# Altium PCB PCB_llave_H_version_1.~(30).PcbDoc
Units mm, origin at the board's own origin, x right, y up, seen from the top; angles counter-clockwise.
Board outline 232.16 x 155.45 mm, 2 copper layers (Top Layer, Bottom Layer); 51 components, 32 nets, 157 pads, 0 vias.
Unrouted connection lines stored in the file: 59.
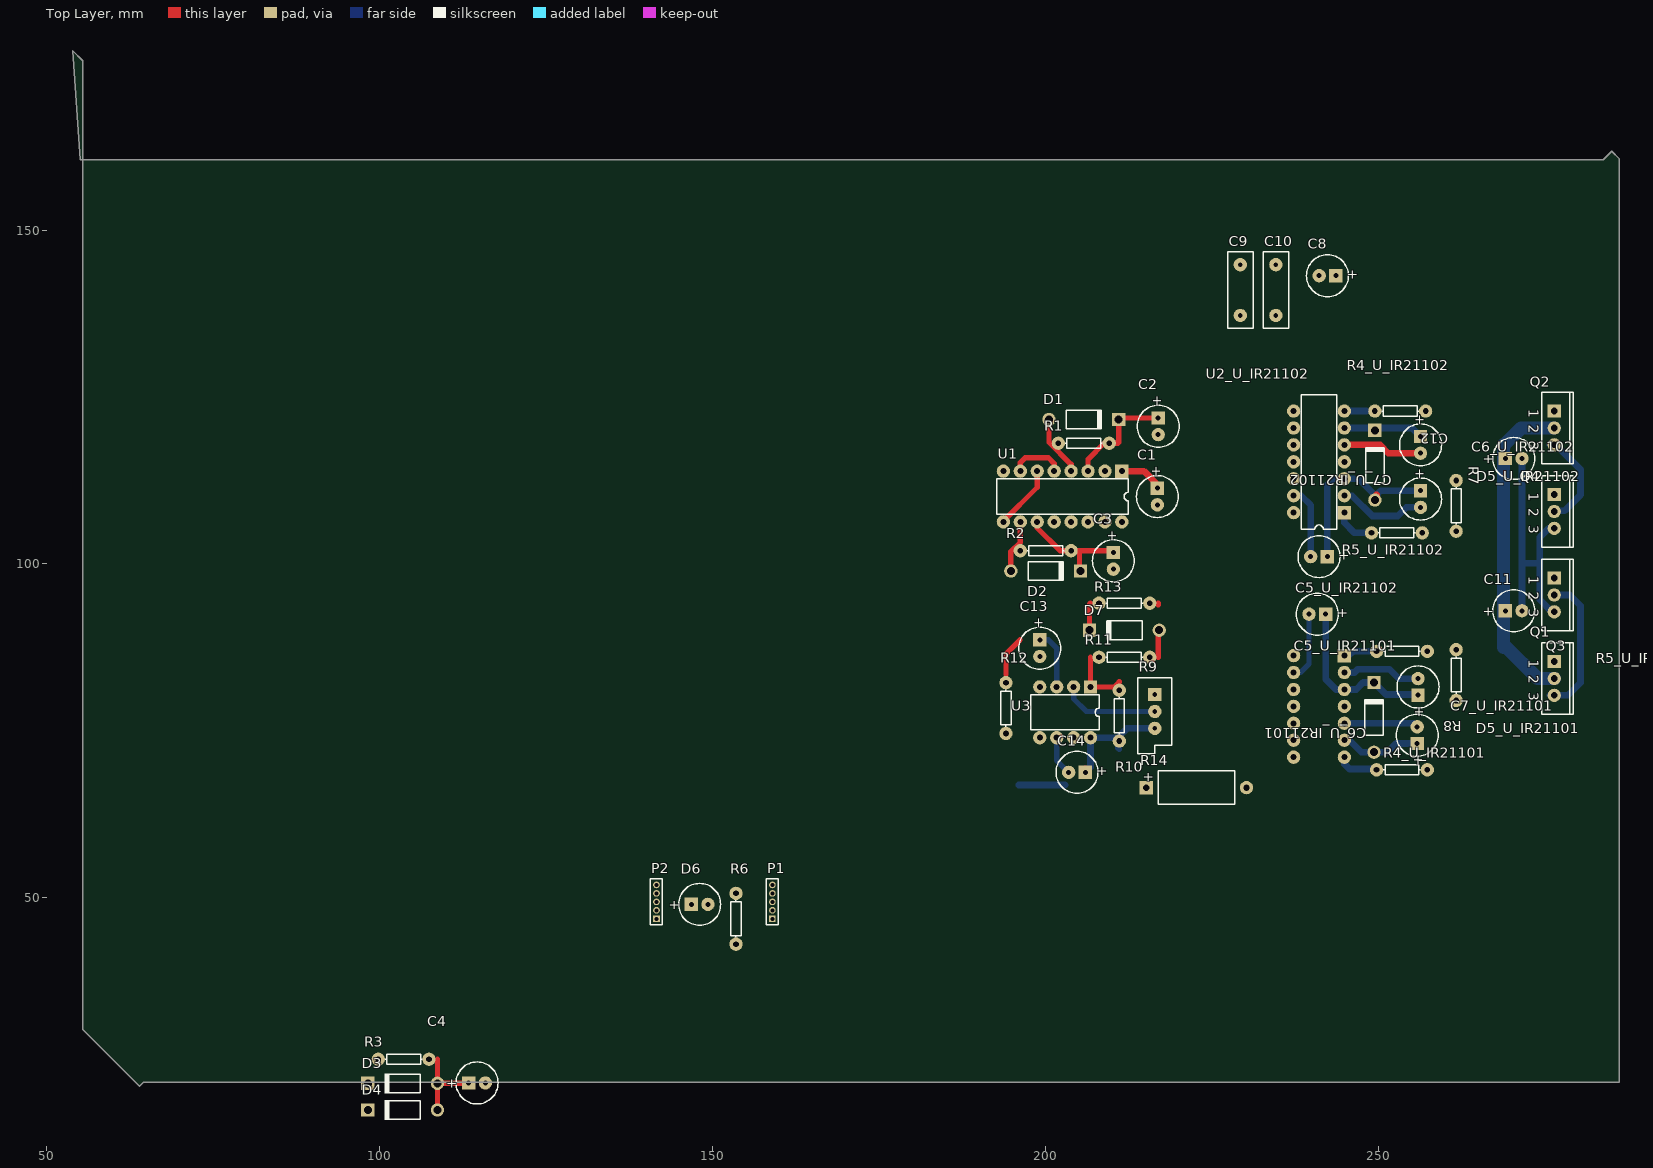
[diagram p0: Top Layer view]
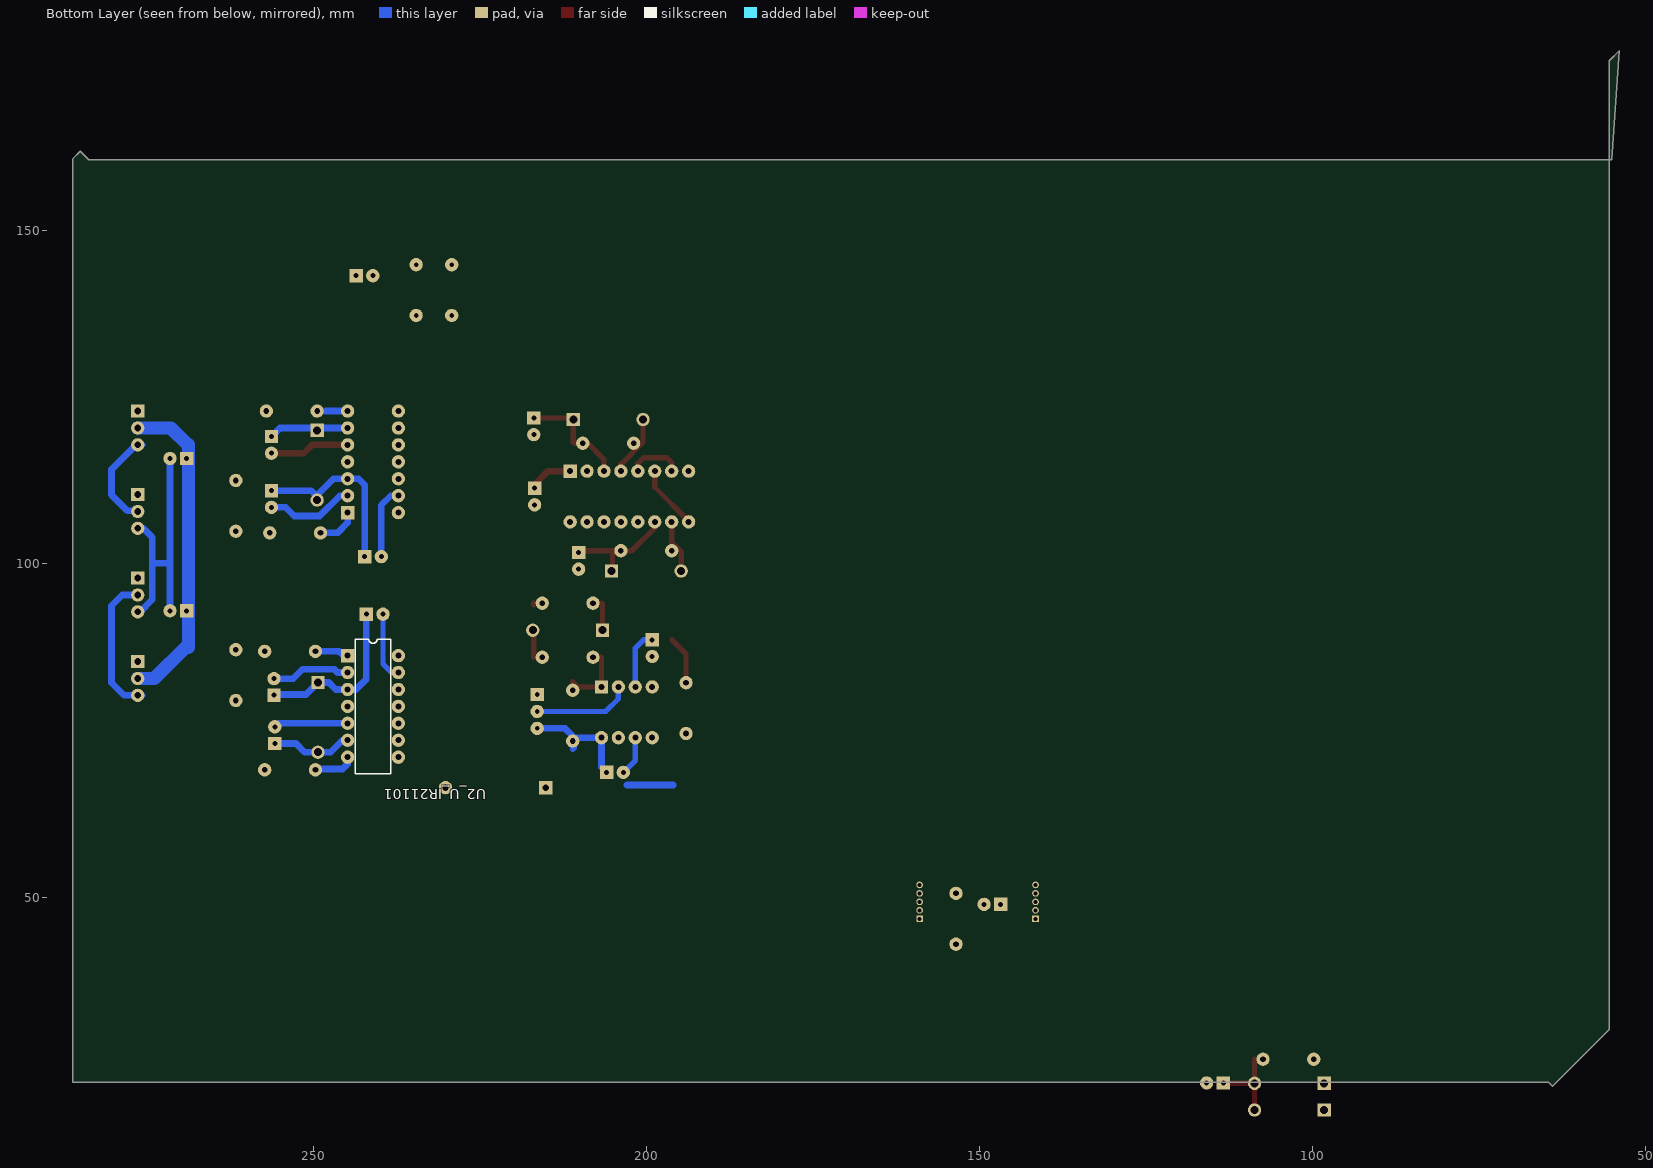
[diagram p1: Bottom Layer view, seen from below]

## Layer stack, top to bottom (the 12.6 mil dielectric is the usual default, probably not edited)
Top Layer: signal copper 0.0356
Dielectric: dielectric 0.32, FR-4, Dk 4.8
Bottom Layer: signal copper 0.0356

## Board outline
53.975,177.038 55.499,175.514 55.499,30.099 64.008,21.59 64.643,22.225 286.131,22.225 286.131,160.782 284.988,161.925 283.718,160.655 55.118,160.655

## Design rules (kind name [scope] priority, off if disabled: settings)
Clearance [All] p1: gap=0.4
ComponentClearance [All] p1: gap=0.254 collisioncheckmode=2 verticalgap=0.254
PolygonConnect [All] p1: connectstyle=Relief reliefconductorwidth=0.254 reliefentries=4 polygonreliefangle="90 Angle"
RoomDefinition U_IR21102 [InComponentClass('U_IR21102')] p1: confinementstyle=ConfineIn formatcopy=TRUE lockcomponents=FALSE outline 233.934,127 260.731,127 260.731,97.282 233.934,97.282
RoomDefinition U_Puente_H [InComponentClass('U_Puente_H')] p2: confinementstyle=ConfineOut formatcopy=TRUE lockcomponents=FALSE outline 287.274,23.114 304.927,23.114 304.927,32.512 287.274,32.512
RoomDefinition U_INITShutdown [InComponentClass('U_INITShutdown')] p3: confinementstyle=ConfineIn formatcopy=TRUE lockcomponents=FALSE outline 90.297,32.893 141.097,32.893 141.097,13.97 90.297,13.97
RoomDefinition U_Shutdown [InComponentClass('U_Shutdown')] p4: confinementstyle=ConfineIn formatcopy=TRUE lockcomponents=FALSE outline 182.88,100.33 233.68,100.33 233.68,62.611 182.88,62.611
RoomDefinition Llave_H_esquema [InComponentClass('Llave_H_esquema')] p5: confinementstyle=ConfineIn formatcopy=TRUE lockcomponents=FALSE outline 140.462,38.481 160.782,38.481 160.782,55.499 140.462,55.499
RoomDefinition U_4049 [InComponentClass('U_4049')] p6: confinementstyle=ConfineIn formatcopy=TRUE lockcomponents=FALSE outline 183.261,95.123 224.917,95.123 224.917,127.889 183.261,127.889
RoomDefinition U_IR21101 [InComponentClass('U_IR21101')] p7: confinementstyle=ConfineIn formatcopy=TRUE lockcomponents=FALSE outline 233.934,96.393 260.731,96.393 260.731,65.786 233.934,65.786
RoutingVias [All] p1: holewidth=0.711 width=1.27 viastyle="Through Hole" minholewidth=0.711 minwidth=1.27 maxholewidth=0.711 maxwidth=1.27
SolderMaskExpansion [All] p1: expansion=0.102
TestPointUsage [All] p1: valid=0 allowmultiple=FALSE
Testpoint [All] p1: side=15 testpointundercomponent=TRUE minsize=1.016 maxsize=2.54 preferedsize=1.524 minholesize=0 maxholesize=1.016 preferedholesize=0.813 testpointgrid=0.025 style=1023 order=0-112345678
Width [All] p1: maxlimit=3 minlimit=0.8 preferedwidth=1
18 further rules are at their usual default settings.

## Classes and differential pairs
component class U_INITShutdown: C4 D3 D4 R3
channel class IR2110: U_IR21101 U_IR21102
component class U_Shutdown: C13 C14 D7 R9 R10 R11 R12 R13 R14 U3
component class U_Puente_H: C8 C9 C10 C11 C12 Q1 Q2 Q3 Q4 R7 R8
component class U_IR21102: C5_U_IR21102 C6_U_IR21102 C7_U_IR21102 D5_U_IR21102 R4_U_IR21102 R5_U_IR21102 U2_U_IR21102
component class U_IR21101: C5_U_IR21101 C6_U_IR21101 C7_U_IR21101 D5_U_IR21101 R4_U_IR21101 R5_U_IR21101 U2_U_IR21101
component class U_4049: C1 C2 C3 D1 D2 R1 R2 U1
component class Llave_H_esquema: D6 P1 P2 R6

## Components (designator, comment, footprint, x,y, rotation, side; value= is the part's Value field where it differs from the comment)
C1 "Cap Pol1" CAPPR2.5-6.3X5 216.789,110.109 r270 top
C2 "Cap Pol1" CAPPR2.5-6.3X5 216.916,120.65 r270 top
C3 "Cap Pol1" CAPPR2.5-6.3X5 210.185,100.457 r270 top
C4 "Cap Pol1" CAPPR2.5-6.3X5 114.681,22.098 r0 top
C5_U_IR21101 "Cap Pol1" CAPPR2.5-6.3X5 240.792,92.456 r180 top (schematic designator C5)
C5_U_IR21102 "Cap Pol1" CAPPR2.5-6.3X5 241.046,101.092 r180 top (schematic designator C5)
C6_U_IR21101 "Cap Pol1" CAPPR2.5-6.3X5 255.778,74.295 r90 top (schematic designator C6)
C6_U_IR21102 "Cap Pol1" CAPPR2.5-6.3X5 256.286,117.856 r270 top (schematic designator C6)
C7_U_IR21101 "Cap Pol1" CAPPR2.5-6.3X5 255.905,81.534 r90 top (schematic designator C7)
C7_U_IR21102 "Cap Pol1" CAPPR2.5-6.3X5 256.286,109.728 r270 top (schematic designator C7)
C8 "Cap Pol1" CAPPR2.5-6.3X5 242.316,143.256 r180 top
C9 "Cap" RAD-0.3 229.235,141.097 r90 top
C10 "Cap" RAD-0.3 234.569,141.097 r90 top
C11 "Cap Pol1" CAPPR2.5-6.3X5 270.256,92.964 r0 top
C12 "Cap Pol1" CAPPR2.5-6.3X5 270.256,115.824 r0 top
C13 "Cap Pol1" CAPPR2.5-6.3X5 199.136,87.356 r270 top
C14 "Cap Pol1" CAPPR2.5-6.3X5 204.724,68.707 r180 top
D1 "Diode" DO-204AL 205.74,121.666 r0 top
D2 "Diode" DO-204AL 200.025,98.933 r0 top
D3 "Diode" DO-204AL 103.505,22.036 r180 top
D4 "Diode" DO-204AL 103.505,18.034 r180 top
D5_U_IR21101 "Diode" DO-204AL 249.301,76.962 r90 top (schematic designator D5)
D5_U_IR21102 "Diode" DO-204AL 249.428,114.808 r90 top (schematic designator D5)
D6 "LED0" CAPPR2.5-6.3X5 148.082,48.895 r0 top
D7 "Diode" DO-204AL 211.836,90.043 r180 top
P1 "MHDR1X5" MHDR1X5 159.004,46.736 r90 top
P2 "MHDR1X5" MHDR1X5 141.605,46.736 r90 top
Q1 "IRF3205" TO-220AB 276.352,82.804 r270 top
Q2 "IRF3205" TO-220AB 276.352,120.396 r270 top
Q3 "IRF3205" TO-220AB 276.352,95.335 r270 top
Q4 "IRF3205" TO-220AB 276.352,107.865 r270 top
R1 "Res2" AXIAL-0.3 205.74,118.11 r180 top
R2 "Res2" AXIAL-0.3 200.025,101.981 r0 top
R3 "Res2" AXIAL-0.3 103.661,25.654 r180 top
R4_U_IR21101 "Res2" AXIAL-0.3 253.492,69.088 r0 top (schematic designator R4)
R4_U_IR21102 "Res2" AXIAL-0.3 253.238,122.936 r0 top (schematic designator R4)
R5_U_IR21101 "Res2" AXIAL-0.3 253.492,86.868 r0 top (schematic designator R5)
R5_U_IR21102 "Res2" AXIAL-0.3 252.73,104.648 r0 top (schematic designator R5)
R6 "Res2" AXIAL-0.3 153.543,46.736 r90 top
R7 "Res2" AXIAL-0.3 261.62,108.712 r270 top
R8 "Res2" AXIAL-0.3 261.62,83.312 r90 top
R9 "RPot" VR5 216.408,77.851 r270 top
R10 "Res2" AXIAL-0.3 211.074,77.216 r270 top
R11 "Res2" AXIAL-0.3 211.836,85.979 r0 top
R12 "Res2" AXIAL-0.3 194.056,78.359 r90 top
R13 "Res2" AXIAL-0.3 211.836,94.107 r180 top
R14 "Res2" CAPPA15.05-11.5x5 222.631,66.421 r0 top
U1 "MC54HC4049J" 620-09 202.565,110.109 r180 top
U2_U_IR21101 "IR2110" PDIP14 241.046,78.613 r270 bottom (schematic designator U2)
U2_U_IR21102 "IR2110" PDIP14 241.046,115.316 r90 top (schematic designator U2)
U3 "LM393N" 626-05 202.946,77.724 r180 top

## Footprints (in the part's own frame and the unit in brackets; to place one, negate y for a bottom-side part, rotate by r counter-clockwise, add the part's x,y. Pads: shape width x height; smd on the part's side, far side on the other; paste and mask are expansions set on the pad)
620-09 [mm] "DIP; 16 Leads; Row Spacing 7.62 mm; Pitch 2.54 mm"
  rect 2x2 hole 0.9: 1(-8.89,-3.81)
  round 2 hole 0.9: 2(-6.35,-3.81) 3(-3.81,-3.81) 4(-1.27,-3.81) 5(1.27,-3.81) 6(3.81,-3.81) 7(6.35,-3.81) 8(8.89,-3.81) 9(8.89,3.81) 10(6.35,3.81) 11(3.81,3.81) 12(1.27,3.81) 13(-1.27,3.81) 14(-3.81,3.81) 15(-6.35,3.81) 16(-8.89,3.81)
  silkscreen extent -9.85,-2.65 9.85,2.65
626-05 [mm] "DIP; 8 Leads; Row Spacing 7.62 mm; Pitch 2.54 mm"
  rect 2x2 hole 0.9: 1(-3.81,-3.81)
  round 2 hole 0.9: 2(-1.27,-3.81) 3(1.27,-3.81) 4(3.81,-3.81) 5(3.81,3.81) 6(1.27,3.81) 7(-1.27,3.81) 8(-3.81,3.81)
  silkscreen extent -5.15,-2.65 5.15,2.65
AXIAL-0.3 [mm] "Resistor; 2 Leads"
  round 2 hole 0.85: 1(-3.81,0) 2(3.81,0)
  silkscreen extent -2.77,-0.76 2.77,0.76
CAPPA15.05-11.5x5 [mm] "Capacitor, Electrolytic, Axial; Body 11.5 x 5 mm (LxDia. max), Lead Dia. 0.6 mm (typ)"
  rect 2x2 hole 0.95: 1(-7.525,0)
  round 2 hole 0.95: 2(7.525,0)
  silkscreen extent -5.75,-2.5 5.75,2.5
CAPPR2.5-6.3X5 [mm] "Capacitor, Electrolytic, Radial; Body 6.3 x 5 mm (Dia.xH typ); Pin Spacing 2.5 mm (typ)"
  rect 2x2 hole 0.75: 1(-1.25,0)
  round 2 hole 0.75: 2(1.25,0)
  silkscreen extent -3.15,-3.15 3.15,3.15
DO-204AL [mm] "Diode, Axial; Body 5.2 x 2.7 mm (LxDia. max), Lead Dia. 0.86 mm (max)"
  round 2 hole 1.2: 1(-5.23,0)
  rect 2x2 hole 1.2: 2(5.23,0)
  silkscreen extent -2.65,-1.4 2.75,1.4
MHDR1X5 [mm] "Connector; Header; 5 Position"
  rect 1x1 hole 0.6: 1(0,0)
  round 1 hole 0.6: 2(1.27,0) 3(2.54,0) 4(3.81,0) 5(5.08,0)
  silkscreen extent -0.9,-0.9 5.98,0.9
PDIP14 [mm] "DIP; 14 Leads; Row Spacing 7.62 mm; Pitch 2.54 mm"
  rect 2x2 hole 0.9: 1(-7.62,-3.81)
  round 2 hole 0.9: 2(-5.08,-3.81) 3(-2.54,-3.81) 4(0,-3.81) 5(2.54,-3.81) 6(5.08,-3.81) 7(7.62,-3.81) 8(7.62,3.81) 9(5.08,3.81) 10(2.54,3.81) 11(0,3.81) 12(-2.54,3.81) 13(-5.08,3.81) 14(-7.62,3.81)
  silkscreen extent -10.1,-2.65 10.1,2.65
RAD-0.3 [mm] "Capacitor; 2 Leads"
  round 2 hole 0.7: 1(-3.81,0) 2(3.81,0)
  silkscreen extent -5.71,-1.91 5.71,1.91
TO-220AB [mm] "TO, Thru-Hole, Vertical, Heatsink Mounted; 3 In-Line Leads; Pitch 2.54 mm"
  rect 2x2 hole 1: 1(-2.54,0)
  round 2 hole 1: 2(0,0) 3(2.54,0)
  silkscreen extent -5.35,-1.85 5.35,2.85
VR5 [mm] "Potentiometer; 3 Leads"
  rect 2x2 hole 0.7: 1(-2.54,0)
  round 2 hole 0.7: 2(2.54,0) 3(0,0)
  silkscreen extent -5.08,-2.54 6.35,2.54

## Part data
C1 C2 C3 C4 C5_U_IR21101 C5_U_IR21102 C6_U_IR21101 C6_U_IR21102 C7_U_IR21101 C7_U_IR21102 C8 C11 C12 C13 C14: "Polarized Capacitor (Radial)"
C9 C10: "Capacitor"
D1 D2 D3 D4 D5_U_IR21101 D5_U_IR21102 D7: "Default Diode"
D6: "Typical INFRARED GaAs LED"
P1 P2: "Header, 5-Pin"
Q1 Q2 Q3 Q4: "HEXFET Power MOSFET"
R1 R2 R3 R4_U_IR21101 R4_U_IR21102 R5_U_IR21101 R5_U_IR21102 R6 R7 R8 R10 R11 R12 R13 R14: "Resistor"
R9: "Potentiometer"
U1: "Hex Inverting Buffer/Logic-Level Down Converter"
U2_U_IR21101 U2_U_IR21102: "High and Low Side Driver"
U3: "Dual Comparator"

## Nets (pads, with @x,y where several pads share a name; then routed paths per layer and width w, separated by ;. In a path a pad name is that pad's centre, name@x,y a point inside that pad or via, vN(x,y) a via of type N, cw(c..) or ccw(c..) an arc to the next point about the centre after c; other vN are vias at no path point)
COM_U_IR21101: C7_U_IR21101.2 C7_U_IR21102.2 C11.2 C12.2 Q3.3 Q4.3 R7.1 R8.1 R12.1 R14.2 U2_U_IR21101.2 U2_U_IR21102.2 | length 72.8
  Bottom Layer w1: 195.981,66.822 202.926,66.822 ; U2_U_IR21101.2 246.38,83.693 246.888,84.201 251.587,84.201 253.004,82.784 C7_U_IR21101.2 ; U2_U_IR21102.2 245.999,110.236 249.047,107.188 252.857,107.188 254.147,108.478 C7_U_IR21102.2 ; C11.2 C12.2 ; 271.506,100.076 274.193,100.076 ; Q4.3 275.505,105.325 274.193,104.013 274.193,94.615 276.013,92.795 Q3.3@276.564,92.795
GND: C1.2 C2.2 C3.2 C4.2 C5_U_IR21101.2 C5_U_IR21102.2 C8.2 C9.1 C10.1 C13.2 C14.2 D6.2 P1.1 P2.4 R9.1 R13.1 R14.1 U1.8 U2_U_IR21101.13 U2_U_IR21102.13 U3.4 U3.5 U3.6 | length 27.5
  Top Layer w0.8: U3.5 199.156,73.934 U3.5@199.136,73.954 ; U3.6@201.656,73.934 U3.6 ; 216.916,93.853 216.916,94.107
  Bottom Layer w0.8: U3.6 201.676,70.505 C14.2 ; U2_U_IR21101.13 238.252,83.693 239.542,84.983 C5_U_IR21101.2
  Bottom Layer w1: U2_U_IR21102.13 238.379,110.236 239.796,108.819 C5_U_IR21102.2
HIN_U_IR21101: U1.12 U2_U_IR21101.10 U2_U_IR21102.12
HIN_U_IR21102: U1.2 U2_U_IR21101.12 U2_U_IR21102.10
HO1: Q2.1 R4_U_IR21102.2
HO2: Q1.1 R4_U_IR21101.2
IN_SD: D4.2 P2.3
LO1: Q4.1 R5_U_IR21102.2 R7.2
LO2: Q3.1 R5_U_IR21101.2 R8.2
MOTOR+: C6_U_IR21102.2 Q2.3 Q4.2 U2_U_IR21102.5 | length 26.7
  Top Layer w1: U2_U_IR21102.5 250.19,117.856 251.44,116.606 C6_U_IR21102.2
  Bottom Layer w1: Q2.3@275.717,117.856 276.606,117.856 280.289,114.173 280.289,110.363 277.876,107.95 Q4.2@276.437,107.95
MOTOR-: C6_U_IR21101.2 Q1.3 Q3.2 U2_U_IR21101.5 | length 32.7
  Bottom Layer w1: U2_U_IR21101.5 255.25,76.073 C6_U_IR21101.2 ; Q1.3@275.717,80.264 278.384,80.264 280.289,82.169 280.289,93.726 278.68,95.335 Q3.2
NetC2_1: C2.1 D1.2 R1.1 U1.3 | length 16.9
  Top Layer w0.8: U1.3 206.375,115.697 208.788,118.11 210.82,118.11 210.97,118.26 D1.2 211.204,121.9 C2.1
NetC3_1: C3.1 D2.2 R2.2 U1.11 | length 17
  Top Layer w0.8: U1.11 198.755,105.41 202.184,101.981 209.911,101.981 C3.1 ; 205.105,101.981 205.105,99.083 D2.2
NetC4_1: C4.1 D3.1 D4.1 R3.1 | length 12.8
  Top Layer w0.8: D3.1@108.429,22.342 D3.1 113.369,22.036 C4.1 ; D4.1 108.741,18.04 108.741,25.654
NetC6_U_IR21101_1: C6_U_IR21101.1 D5_U_IR21101.2 U2_U_IR21101.6 | length 12.2
  Bottom Layer w1: U2_U_IR21101.6 245.618,73.533 247.419,71.732 251.31,71.732 252.623,73.045 C6_U_IR21101.1
NetC6_U_IR21102_1: C6_U_IR21102.1 D5_U_IR21102.2 U2_U_IR21102.6 | length 12.2
  Top Layer w0.8: D5_U_IR21102.2@249.532,120.396 D5_U_IR21102.2@249.682,120.546
  Bottom Layer w1: U2_U_IR21102.6 254.996,120.396 C6_U_IR21102.1
NetC13_1: C13.1 R12.2 U3.3 | length 15.1
  Top Layer w0.8: 194.056,83.439 194.056,86.487 196.175,88.606 ; C13.1 C13.1@199.223,88.519
  Bottom Layer w0.8: C13.1 200.446,88.606 201.676,87.376 U3.3
NetD1_1: D1.1 R1.2 U1.4 | length 9.1
  Top Layer w0.8: D1.1 200.51,118.26 203.835,114.935 U1.4
NetD2_1: D2.1 R2.1 U1.10 | length 8
  Top Layer w0.8: D2.1 194.795,101.831 196.215,103.251 U1.10
NetD6_1: D6.1 R6.1
NetD7_1: D7.1 R11.2 | length 4.2
  Top Layer w0.8: 216.916,85.979 D7.1@216.916,90.17
NetR4_U_IR21101_1: R4_U_IR21101.1 U2_U_IR21101.7 | length 6
  Top Layer w1: U2_U_IR21101.7@244.856,70.866 U2_U_IR21101.7
  Bottom Layer w1: U2_U_IR21101.7 244.856,69.977 245.618,69.215 R4_U_IR21101.1@249.428,69.215
NetR4_U_IR21102_1: R4_U_IR21102.1 U2_U_IR21102.7 | length 3.3
  Bottom Layer w1: U2_U_IR21102.7 248.158,122.936
NetR5_U_IR21101_1: R5_U_IR21101.1 U2_U_IR21101.1 | length 5.1
  Bottom Layer w1: U2_U_IR21101.1 245.491,86.233 246.126,86.868 R5_U_IR21101.1
NetR5_U_IR21102_1: R5_U_IR21102.1 U2_U_IR21102.1 | length 6.2
  Bottom Layer w1: U2_U_IR21102.1 244.856,106.172 246.38,104.648 R5_U_IR21102.1
NetR9_3: R9.3 U3.2 | length 14.8
  Bottom Layer w0.8: U3.2 204.216,79.756 206.121,77.851 R9.3
NetR10_1: R10.1 R11.1 U3.1 | length 9.1
  Top Layer w0.8: 206.756,85.979 U3.1 210.312,81.534 211.074,82.296
NetU1_6: U1.6 U1.9 | length 9.7
  Top Layer w0.8: U1.9 193.675,106.426 198.755,111.506 U1.6
PWM: P2.2 U1.5 U1.7 | length 8.2
  Top Layer w0.8: U1.7 196.215,115.189 196.977,115.951 200.406,115.951 201.295,115.062 U1.5
SD: D3.2 D7.2 R13.2 U2_U_IR21101.11 U2_U_IR21102.11 | length 4.1
  Top Layer w0.8: D7.2 206.606,93.957 206.756,94.107
VCC_MOTOR: C8.1 C9.2 C10.2 C11.1 C12.1 P1.2 Q1.2 Q2.2 | length 48.1
  Bottom Layer w2: 268.732,87.503 268.732,117.876 ; 269.006,87.63 273.832,82.804 Q1.2 ; 269.006,118.003 271.399,120.396 Q2.2
VDD: C1.1 C5_U_IR21101.1 C5_U_IR21102.1 C7_U_IR21101.1 C7_U_IR21102.1 C14.1 D5_U_IR21101.1 D5_U_IR21102.1 P2.5 R3.2 R6.2 R9.2 R10.2 U1.1 U2_U_IR21101.3 U2_U_IR21101.9 U2_U_IR21102.3 U2_U_IR21102.9 U3.8 | length 79.9
  Top Layer w0.8: C14.1 C14.1@205.974,69.322 ; U3.8@206.629,74.168 206.756,74.041 U3.8 ; C1.1 C1.1@216.789,111.76
  Top Layer w1: U1.1 214.757,113.919 216.789,111.887 C1.1 ; D5_U_IR21102.1@249.682,110.086 D5_U_IR21102.1@249.682,110.363
  Bottom Layer w0.8: R10.2@210.82,73.914 210.82,72.39 211.074,72.136 211.074,74.133 R10.2@211.056,74.15
  Bottom Layer w1: C14.1 206.756,69.489 U3.8 R10.2@210.82,73.914 ; R10.2@211.056,74.15 212.217,75.311 R9.2 ; C5_U_IR21101.1 242.042,82.697 243.586,81.153 246.634,81.153 247.673,82.192 249.301,82.192 251.102,80.391 255.798,80.391 C7_U_IR21101.1 ; C5_U_IR21102.1 242.296,111.867 243.205,112.776 U2_U_IR21102.3 246.992,112.776 249.682,110.086 249.682,110.363 250.297,110.978 C7_U_IR21102.1
pads on no net: P1.3 P1.4 P1.5 P2.1 U1.13 U1.14 U1.15 U1.16 U2_U_IR21101.4 U2_U_IR21101.8 U2_U_IR21101.14 U2_U_IR21102.4 U2_U_IR21102.8 U2_U_IR21102.14 U3.7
